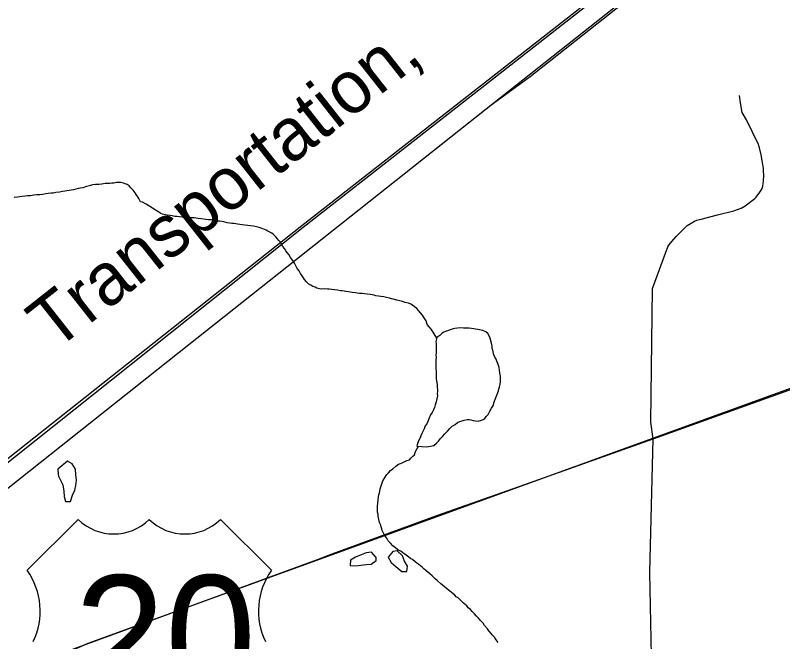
# Model space of a CAD drawing. Extents: x 0 to 44.3, y 0 to 22.
# Drawn here: x 7.197 to 8.026, y 19.675 to 20.352 of the extents above; entities that cross this region are included whole.
import ezdxf

# ---------------------------------------------------------------- set-up
doc = ezdxf.new("R2010")
doc.units = 0
for name, color, linetype in [('GM_X_City_Street', 7, 'Continuous'), ('GM_X_Minor_Lake', 7, 'Continuous'), ('GM_X_Minor_River', 7, 'Continuous'), ('GM_X_Rail_Line', 7, 'Continuous'), ('GM_X_Rail_Line_Text', 7, 'Continuous'), ('GM_X_US_Location', 7, 'Continuous'), ('GM_X_US_Route', 7, 'Continuous'), ('GM_X_US_Shield', 7, 'Continuous')]:
    doc.layers.add(name, color=color, linetype=linetype)

msp = doc.modelspace()

# ---------------------------------------------------------------- linework, layer by layer
at = {"layer": 'GM_X_City_Street'}
for points in [[(7.88659, 19.8941), (7.884, 19.91222), (7.88562, 20.05656), (7.90216, 20.10191), (7.90334, 20.10366), (7.90655, 20.10763), (7.91117, 20.11301), (7.91552, 20.11737), (7.91911, 20.12096), (7.92334, 20.12467), (7.9277, 20.12749), (7.93117, 20.12954), (7.93373, 20.13069), (7.93655, 20.13146), (7.93823, 20.13182), (7.95598, 20.13649), (7.97374, 20.14077), (7.97654, 20.14175), (7.9814, 20.14355), (7.98577, 20.14605), (7.9962, 20.15395), (7.99769, 20.15547), (8.0018, 20.16085), (8.00321, 20.16315), (8.00426, 20.16483), (8.005, 20.16751), (8.00564, 20.17302), (8.00603, 20.17892), (8.00563, 20.18429), (8.00553, 20.18687), (8.00463, 20.19263), (8.00399, 20.19725), (8.00323, 20.20135), (8.00143, 20.20891), (8.00029, 20.21234), (7.98739, 20.23903), (7.98261, 20.2469), (7.9808, 20.25752), (7.97981, 20.26549)], [(7.82598, 18.31355), (7.83814, 18.33772), (7.84162, 18.34472), (7.8426, 18.34733), (7.84391, 18.35061), (7.84494, 18.35313), (7.85369, 18.51403), (7.85512, 18.57209), (7.85625, 18.61648), (7.85812, 18.91062), (7.87455, 19.3646), (7.88413, 19.55922), (7.88565, 19.60564), (7.88294, 19.74986), (7.88659, 19.8941)]]:
    msp.add_lwpolyline(points, dxfattribs=at)
at = {"layer": 'GM_X_Minor_Lake'}
for points in [[(7.71935, 19.94621), (7.71948, 19.94676), (7.72053, 19.9506), (7.72122, 19.95328), (7.72153, 19.95596), (7.72146, 19.95862), (7.72138, 19.96204), (7.72092, 19.96508), (7.72045, 19.9685), (7.71999, 19.97153), (7.71915, 19.97455), (7.71834, 19.97644), (7.71753, 19.97832), (7.71672, 19.9802), (7.71552, 19.98246), (7.71471, 19.98434), (7.7139, 19.98622), (7.71346, 19.9885), (7.7126, 19.99228), (7.71254, 19.99457), (7.71171, 19.99759), (7.71084, 20.00176), (7.71002, 20.00402), (7.70801, 20.00816), (7.70567, 20.01001), (7.70259, 20.01145), (7.70067, 20.01178), (7.69723, 20.01246), (7.69456, 20.01277), (7.69264, 20.0131), (7.69035, 20.01343), (7.68767, 20.01374), (7.68462, 20.01404), (7.68157, 20.01396), (7.67852, 20.01426), (7.6751, 20.0138), (7.67206, 20.01334), (7.66941, 20.01289), (7.66223, 20.01042), (7.66035, 20.00961), (7.65848, 20.00842), (7.65587, 20.00607), (7.65288, 20.00371), (7.65185, 19.9995), (7.65191, 19.99721), (7.65196, 19.99493), (7.65204, 19.99188), (7.6521, 19.9896), (7.65216, 19.98732), (7.65185, 19.98464), (7.6519, 19.98236), (7.6516, 19.9793), (7.65166, 19.97702), (7.65173, 19.97436), (7.65179, 19.97207), (7.65185, 19.96941), (7.6519, 19.96751), (7.65206, 19.96142), (7.65212, 19.95914), (7.65256, 19.95686), (7.65261, 19.95496), (7.65304, 19.95269), (7.65311, 19.95002), (7.65356, 19.94737), (7.65361, 19.94546), (7.65329, 19.94317), (7.65335, 19.94089), (7.65199, 19.93438), (7.65094, 19.93093), (7.65024, 19.92824), (7.64917, 19.92555), (7.64771, 19.92285), (7.64588, 19.92013), (7.64408, 19.9159), (7.64302, 19.91282), (7.64193, 19.91051), (7.64009, 19.90818), (7.63903, 19.90511), (7.63794, 19.90279), (7.63649, 19.90009), (7.63541, 19.8974), (7.6347, 19.89548), (7.63289, 19.892), (7.63217, 19.89008), (7.63147, 19.88778), (7.63113, 19.88625)], [(7.68944, 19.91477), (7.69213, 19.91408), (7.69442, 19.91375), (7.69748, 19.91345), (7.70089, 19.9143), (7.70277, 19.91511), (7.70464, 19.9163), (7.70612, 19.91824), (7.70834, 19.92058), (7.71016, 19.92406), (7.71197, 19.92753), (7.7138, 19.93062), (7.71449, 19.93331), (7.71935, 19.94621)], [(7.63113, 19.88625), (7.64181, 19.88576), (7.64371, 19.88581), (7.64599, 19.88625), (7.64939, 19.88709), (7.65238, 19.88945), (7.6546, 19.8918), (7.65682, 19.89452), (7.65905, 19.89686), (7.66126, 19.89958), (7.66423, 19.9027), (7.66683, 19.90543), (7.66943, 19.90779), (7.67243, 19.90977), (7.67505, 19.91174), (7.67768, 19.91295), (7.67995, 19.91377), (7.68221, 19.91459), (7.68563, 19.91505), (7.68753, 19.9151), (7.68944, 19.91477)], [(7.25371, 19.87), (7.24343, 19.8616), (7.24349, 19.8559), (7.24406, 19.85375)], [(7.25708, 19.82642), (7.25929, 19.83328), (7.26151, 19.83862), (7.26259, 19.84395), (7.26329, 19.84965), (7.26286, 19.85535), (7.26241, 19.86142), (7.25894, 19.86708), (7.25371, 19.87)], [(7.24406, 19.85375), (7.24854, 19.84456), (7.24975, 19.83774), (7.25019, 19.83204), (7.25139, 19.82636), (7.25708, 19.82642)], [(7.58736, 19.76589), (7.58219, 19.77174), (7.5765, 19.77092), (7.57112, 19.7687)], [(7.60514, 19.77247), (7.60366, 19.77053)], [(7.62022, 19.75083), (7.62092, 19.75654), (7.61782, 19.7622), (7.61549, 19.76787), (7.60974, 19.77313), (7.60514, 19.77247)], [(7.57112, 19.7687), (7.56478, 19.76624), (7.5595, 19.76315)], [(7.57355, 19.75795), (7.57663, 19.75839), (7.58194, 19.75883), (7.58721, 19.76268), (7.58736, 19.76589)], [(7.60366, 19.77053), (7.60032, 19.76619), (7.60342, 19.76053), (7.60857, 19.75616)], [(7.5595, 19.76315), (7.55918, 19.75745), (7.56526, 19.75713), (7.57355, 19.75795)], [(7.60857, 19.75616), (7.6149, 19.75078), (7.62022, 19.75083)]]:
    msp.add_lwpolyline(points, dxfattribs=at)
at = {"layer": 'GM_X_Minor_River'}
for points in [[(7.41193, 20.13009), (7.40925, 20.13078), (7.40619, 20.13109), (7.40314, 20.13139), (7.39855, 20.13203), (7.39473, 20.13232), (7.39053, 20.13297), (7.38671, 20.13326), (7.38328, 20.13317), (7.38023, 20.13347), (7.37755, 20.13378), (7.37488, 20.1341), (7.37221, 20.13441), (7.36953, 20.13472), (7.36685, 20.13542), (7.36417, 20.13573), (7.3615, 20.13604), (7.3592, 20.13636), (7.35652, 20.13706), (7.3546, 20.13777), (7.35227, 20.13923), (7.33871, 20.14803), (7.33485, 20.15022), (7.33256, 20.15054), (7.33094, 20.15393), (7.32975, 20.1558), (7.32778, 20.15841), (7.32697, 20.1603), (7.32462, 20.1629), (7.32227, 20.16551), (7.3203, 20.16774), (7.31836, 20.16922), (7.31606, 20.16992), (7.31414, 20.17063), (7.31145, 20.17132), (7.30955, 20.17128), (7.3065, 20.1712), (7.30385, 20.17075), (7.30156, 20.17069), (7.29929, 20.17025), (7.29624, 20.17018), (7.29434, 20.17013), (7.29092, 20.16966), (7.28751, 20.16919), (7.28408, 20.16911), (7.28066, 20.16864), (7.27764, 20.1678), (7.27423, 20.16695), (7.27045, 20.16571), (7.26514, 20.16481), (7.26022, 20.16355), (7.24846, 20.16172), (7.24505, 20.16087), (7.24126, 20.16039), (7.23822, 20.15994), (7.23593, 20.15988), (7.2329, 20.15942), (7.23024, 20.15897), (7.22721, 20.15851), (7.22379, 20.15805), (7.22075, 20.15797), (7.21733, 20.1575), (7.21391, 20.15703), (7.21087, 20.15696), (7.20783, 20.1565), (7.20479, 20.15604), (7.20213, 20.15597), (7.19985, 20.15553), (7.19606, 20.15505)], [(7.65269, 20.00294), (7.64695, 20.01232), (7.64459, 20.0153), (7.64223, 20.01791), (7.64137, 20.0217), (7.63979, 20.02394), (7.63821, 20.02618), (7.6374, 20.02807), (7.63309, 20.03291), (7.63113, 20.03514), (7.62879, 20.03699), (7.62646, 20.03883), (7.62453, 20.03993), (7.62221, 20.04101), (7.6203, 20.04134), (7.61839, 20.04168), (7.61569, 20.04275), (7.61263, 20.04343), (7.60956, 20.04411), (7.60573, 20.04516), (7.60381, 20.04549), (7.60151, 20.04619), (7.59844, 20.04688), (7.59538, 20.04756), (7.59232, 20.04825), (7.58964, 20.04856), (7.58696, 20.04887), (7.58504, 20.04958), (7.58275, 20.0499), (7.58083, 20.05024), (7.5774, 20.05053), (7.57472, 20.05084), (7.57205, 20.05116), (7.56938, 20.05147), (7.5667, 20.05178), (7.56479, 20.05211), (7.56135, 20.0524), (7.55906, 20.05273), (7.55714, 20.05306), (7.55447, 20.05337), (7.55256, 20.05371), (7.55064, 20.05404), (7.54873, 20.05437), (7.54528, 20.05504), (7.54223, 20.05535), (7.5365, 20.05596), (7.53459, 20.05591), (7.53154, 20.05621), (7.52849, 20.05614), (7.52582, 20.05645), (7.52313, 20.05714), (7.5212, 20.05824), (7.5189, 20.05894), (7.51657, 20.0604), (7.51464, 20.0615), (7.51191, 20.06409), (7.50995, 20.06633), (7.50876, 20.0682), (7.50717, 20.07045), (7.50558, 20.07307), (7.50399, 20.0757), (7.50202, 20.07831), (7.50042, 20.08132), (7.49883, 20.08394), (7.49723, 20.08695), (7.49448, 20.09031), (7.49288, 20.09331), (7.49091, 20.09555), (7.48972, 20.09742), (7.48813, 20.10005), (7.48655, 20.10229), (7.48497, 20.10453), (7.48377, 20.10679), (7.4822, 20.10865), (7.48023, 20.11089), (7.47866, 20.11275), (7.47632, 20.11498), (7.47438, 20.11645), (7.47245, 20.11754), (7.47013, 20.11863), (7.4682, 20.11972), (7.46473, 20.12116), (7.46281, 20.12187), (7.46089, 20.12258), (7.45782, 20.12327), (7.45476, 20.12395), (7.4452, 20.12523), (7.44253, 20.12554), (7.43985, 20.12585), (7.43756, 20.12618), (7.43564, 20.12651), (7.43335, 20.12683), (7.43144, 20.12716), (7.42914, 20.12749), (7.42609, 20.12779), (7.42263, 20.12884), (7.42034, 20.12916), (7.41805, 20.12949), (7.41614, 20.12944), (7.41385, 20.12976), (7.41193, 20.13009)], [(7.64104, 19.75208), (7.6391, 19.75355), (7.63676, 19.75539), (7.63326, 19.75835), (7.63132, 19.75983), (7.62938, 19.7613), (7.62664, 19.7639), (7.62472, 19.76461), (7.62239, 19.76645), (7.61811, 19.76977), (7.61618, 19.77086), (7.61385, 19.77271), (7.61115, 19.77378), (7.60804, 19.77637), (7.60531, 19.77858), (7.60257, 19.78156), (7.60022, 19.78417), (7.59863, 19.78679), (7.59626, 19.79016), (7.59506, 19.79241), (7.59385, 19.79505), (7.59342, 19.79694), (7.5926, 19.7992), (7.59217, 19.8011), (7.59096, 19.80373), (7.59011, 19.80714), (7.58926, 19.81054), (7.5892, 19.81282), (7.58876, 19.8151), (7.58871, 19.817), (7.58864, 19.81967), (7.58858, 19.82195), (7.58891, 19.82424), (7.58985, 19.83188), (7.59019, 19.83379), (7.5909, 19.83572), (7.59123, 19.83763), (7.59154, 19.8403), (7.59261, 19.84338), (7.59331, 19.84568), (7.59438, 19.84875), (7.5962, 19.85184), (7.59877, 19.85572), (7.60062, 19.85767), (7.60285, 19.86001), (7.60508, 19.86197), (7.60844, 19.86472), (7.61144, 19.8667), (7.61332, 19.86751), (7.61521, 19.86832), (7.61821, 19.86992), (7.62048, 19.87074), (7.62312, 19.87157), (7.6246, 19.87351), (7.62683, 19.87547), (7.6287, 19.87705), (7.62975, 19.8805), (7.63157, 19.88397), (7.63292, 19.88616)], [(7.71885, 19.6741), (7.71686, 19.67709), (7.71489, 19.67971), (7.71293, 19.68194), (7.71136, 19.6838), (7.709, 19.68679), (7.70742, 19.68903), (7.70428, 19.69238), (7.70269, 19.69501), (7.69995, 19.69798), (7.6976, 19.70059), (7.69564, 19.70244), (7.69329, 19.70505), (7.69094, 19.70765), (7.68898, 19.70989), (7.68664, 19.71173), (7.68507, 19.7136), (7.68157, 19.71656), (7.67883, 19.71953), (7.6757, 19.7225), (7.67377, 19.72359), (7.6722, 19.72545), (7.66987, 19.72692), (7.66676, 19.7295), (7.66287, 19.73283), (7.66092, 19.73431), (7.65897, 19.73616), (7.65703, 19.73763), (7.65314, 19.74096), (7.6508, 19.74281), (7.64767, 19.74615), (7.64533, 19.74838), (7.64299, 19.75022), (7.64104, 19.75208)]]:
    msp.add_lwpolyline(points, dxfattribs=at)
at = {"layer": 'GM_X_Rail_Line'}
for points in [[(5.56513, 18.76798), (5.6149, 18.77572), (5.66544, 18.78761), (5.729, 18.80531), (5.80514, 18.8321), (5.88221, 18.86669), (5.94993, 18.90488), (5.99654, 18.93252), (6.04939, 18.97052), (6.27832, 19.15151), (6.65109, 19.44865), (7.06803, 19.77704), (7.50687, 20.12494), (7.88155, 20.41814), (8.1527, 20.63414), (8.48759, 20.9)], [(5.5655, 18.7657), (5.61535, 18.77344), (5.66602, 18.78537), (5.7297, 18.8031), (5.806, 18.82994), (5.88327, 18.86462), (5.95114, 18.9029), (6.00093, 18.93159), (6.05433, 18.96936), (6.28021, 19.14816), (6.65573, 19.44687), (7.07421, 19.77735), (7.50832, 20.12312), (7.883, 20.41633), (8.15415, 20.63233), (8.49132, 20.9)], [(7.70993, 20.25419), (7.75351, 20.28574), (7.98155, 20.46629), (7.99492, 20.47688), (8.00693, 20.48575), (8.02197, 20.49703), (8.03723, 20.5078), (8.05585, 20.52056), (8.082, 20.53808), (8.10872, 20.55573), (8.21834, 20.62825), (8.2248, 20.63253)], [(5.58839, 18.58756), (5.6031, 18.59446), (5.61773, 18.6024), (5.63079, 18.61006), (5.64402, 18.61868), (5.66457, 18.63303), (5.68102, 18.64553), (6.02464, 18.9178), (6.11534, 18.98987), (6.2212, 19.07364), (6.33867, 19.16676), (6.41276, 19.22554), (6.50701, 19.3002), (6.62061, 19.39017), (6.72711, 19.47491), (7.08412, 19.75765), (7.37444, 19.988), (7.70589, 20.25099), (7.98011, 20.4681), (7.9935, 20.47872), (8.00553, 20.48761), (8.02059, 20.4989), (8.0359, 20.5097)], [(8.9, 20.33755), (8.84921, 20.30037), (8.7465, 20.21938), (8.70662, 20.19157), (8.57462, 20.14396), (8.33119, 20.05636), (7.27582, 19.67296), (7.22627, 19.6512), (6.61974, 19.17899), (6.34339, 18.94899), (5.9721, 18.70685), (5.93802, 18.69104), (5.84794, 18.63141), (5.77124, 18.56813), (5.73351, 18.54623), (5.47425, 18.44649)]]:
    msp.add_lwpolyline(points, dxfattribs=at)
at = {"layer": 'GM_X_US_Route'}
for points in [[(7.88659, 19.8941), (8.07527, 19.96206), (8.13935, 19.98601), (8.30763, 20.04556), (8.36394, 20.06562), (8.40148, 20.07954), (8.44658, 20.09464)], [(7.53967, 19.76982), (7.65261, 19.81125), (7.74161, 19.84264), (7.88659, 19.8941)], [(7.17489, 19.6148), (7.20377, 19.63791), (7.22283, 19.64911), (7.23643, 19.65591), (7.25066, 19.66368), (7.52381, 19.764), (7.53967, 19.76982)]]:
    msp.add_lwpolyline(points, dxfattribs=at)
at = {"layer": 'GM_X_US_Shield'}
for p, q in [((7.26521, 19.80712), (7.21028, 19.75219)), ((7.47395, 19.75219), (7.41902, 19.80712))]:
    msp.add_line(p, q, dxfattribs=at)
for centre, radius, start, end in [((7.30366, 19.84635), 0.05493, 225.573, 314.427), ((7.38057, 19.84635), 0.05493, 225.573, 314.427), ((7.14728, 19.70807), 0.0769, 334.54712, 35.00093), ((7.53695, 19.70807), 0.0769, 144.99907, 205.45288)]:
    msp.add_arc(centre, radius, start, end, dxfattribs=at)

# ---------------------------------------------------------------- texts
at = {"layer": 'GM_X_Rail_Line_Text'}
msp.add_text('Transportation,', height=0.0566288, rotation=38.25928, dxfattribs=at).set_placement((7.23985, 19.98817))
at = {"layer": 'GM_X_US_Location'}
for s, p in [('0', (7.34204, 19.67974)), ('/', (7.34206, 19.67974))]:
    msp.add_text(s, height=0.000189, dxfattribs=at).set_placement(p)
at = {"layer": 'GM_X_US_Shield'}
msp.add_text('20', height=0.131836, dxfattribs=at).set_placement((7.26121, 19.61486))

doc.saveas('drawing.dxf')
